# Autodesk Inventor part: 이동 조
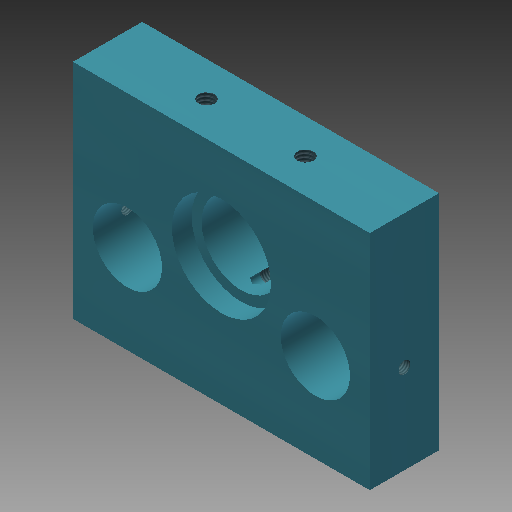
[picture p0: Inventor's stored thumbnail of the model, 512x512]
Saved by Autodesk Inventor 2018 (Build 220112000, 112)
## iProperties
Created: 2020-03
Part Number: 이동 조
Material: 알루미늄 6061
Document SubType Name: Modeling
Designer: mduedu
Density: 2.71 g/cm^3
Mass: 81.3787 g
Surface Area: 95.2757 cm^2
Volume: 30.029 cm^3
Appearance: 커뎃 파란색
Author: mduedu
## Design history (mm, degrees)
sketch "스케치1"
  geometry: L1 (-30, 0)-(30, 0); L2 (30, 0)-(30, 48); L3 (30, 48)-(-30, 48); L4 (-30, 48)-(-30, 0); 2 further points
  constraints: 8 end point, 2 parallel, 1 coincident, 1 horizontal, 1 midpoint, 1 perpendicular
  dimensions: "d0" = 60 distance of L1.start L1.end; "d2" = 48 distance of L1.end L2.end
extrude "돌출1" new body sketch "스케치1" distance "d3" = 14; taper "d4" = 0 deg
sketch "스케치3"
  geometry: L1 (30, 0)-(-30, 0); 3 further points
  constraints: 2 end point, 1 midpoint, 1 vertical alignment
  dimensions: "d15" = 26 distance of point (0, 0) point (0, 26)
hole "구멍2" sketch "스케치3" diameter "d16" = 16; stored, may be unused: countersink angle "d20" = 90 deg, drill point angle "d22" = 118 deg; dims "d17" = 8, "d18" = 20, "d19" = 4, "d21" = 10
sketch "스케치4"
  geometry: 3 further points
  constraints: 1 horizontal alignment
  dimensions: "d23" = 18 vertical distance of point (19, 18) point (0, 0); "d24" = 19 horizontal distance of point (-19, 18) point (0, 0); "d25" = 38 distance of point (19, 18) point (-19, 18)
hole "구멍7" sketch "스케치4" at (-19, 18), (19, 18) diameter "d65" = 14; stored, may be unused: countersink angle "d69" = 90 deg, drill point angle "d71" = 118 deg; dims "d66" = 6, "d67" = 4, "d68" = 2, "d70" = 8
sketch "스케치7"
  geometry: L1 (-18, 48)-(18, 48); L2 (18, 48)-(18, 45); L3 (18, 45)-(-18, 45); L4 (-18, 45)-(-18, 48); L5 (30, 48)-(-30, 48) reference; L6 (-30, 0)-(30, 0) reference; 5 further points
  constraints: 8 end point, 2 midpoint, 2 parallel, 1 collinear, 1 horizontal, 1 perpendicular, 1 vertical alignment
  dimensions: "d50" = 3 distance of L1.end L2.end; "d52" = 36 distance of L1.start L1.end
extrude "돌출2" cut sketch "스케치7" extent not by distance; stored distance "d53" = 10; taper "d54" = 0 deg
sketch "스케치8"
  geometry: 3 further points
  constraints: 1 horizontal alignment
  dimensions: "d55" = 7 vertical distance of point (28, 7) point (18, 14); "d56" = 10 horizontal distance of point (8, 7) point (18, 14); "d57" = 20 distance of point (28, 7) point (8, 7)
hole "구멍6" sketch "스케치8" at (8, 7), (28, 7) diameter "d58" = 3.242; stored, may be unused: countersink angle "d62" = 90 deg, drill point angle "d64" = 118 deg; dims "d59" = 6, "d60" = 4, "d61" = 2, "d63" = 8
sketch "스케치9"
  geometry: 3 further points
  constraints: 2 vertical alignment, 1 other
hole "구멍8" sketch "스케치9" at (0, 18) diameter "d75" = 2.459; stored, may be unused: countersink angle "d79" = 90 deg, drill point angle "d81" = 118 deg; dims "d76" = 5, "d77" = 4, "d78" = 2, "d80" = 7
sketch "스케치10"
  geometry: L1 (14, 0)-(14, 48) reference; L2 (14, 0)-(0, 0) reference; 2 further points
  dimensions: "d82" = 7 distance from line of point (7, 18) L1; "d83" = 18 distance from line of point (7, 18) L2
hole "구멍9" sketch "스케치10" at (7, 18) diameter "d84" = 2.459; stored, may be unused: countersink angle "d88" = 90 deg, drill point angle "d90" = 118 deg; dims "d85" = 8, "d86" = 4, "d87" = 2, "d89" = 10
node "작업 평면1"
sketch "스케치11"
  geometry: L1 (0, 14)-(0, 0) reference; L2 (36, 0)-(0, 0) reference; L3 (48, 0)-(36, 0) reference; L4 (48, 14)-(48, 0) reference; L5 (36, 14)-(48, 14) reference; L6 (36, 0)-(36, 14) reference; L7 (0, 14)-(36, 14) reference; L8 (-12, 14)-(0, 14) reference; L9 (-12, 0)-(-12, 14) reference; L10 (0, 0)-(-12, 0) reference; C1 r 1.621 at (8, 7) reference; C2 r 1.621 at (28, 7) reference; 1 further point
extrude "돌출3" cut sketch "스케치11" extent not by distance; stored distance "d91" = 10; taper "d92" = 0 deg
node "솔리드1"
mirror "대칭1"
node "절단 모서리 투영1"
